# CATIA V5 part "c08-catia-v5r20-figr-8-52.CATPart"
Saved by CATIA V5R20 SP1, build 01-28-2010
Part number: Part1
Bounding box of the stored display mesh (mm): x -37.5 to 37.5, y -150 to 150, z 0 to 10
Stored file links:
  D:\v5_r20\psrt_files_downloaded\c08-catia-v5r20-prt\c08-catia-v5r20-figr-8-52.CATPart
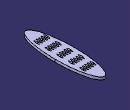
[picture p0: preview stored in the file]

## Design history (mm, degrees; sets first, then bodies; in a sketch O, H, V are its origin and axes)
Body1 (main body)
  Sketch1 on xy-plane, origin (0, 0, 0), H (1, 0, 0), V (0, 1, 0)
    circle A1 centre (0, 0) radius 75
    point P1 (0, 75)
    radius A1 = 75
    coincidence: A1 P1, P1 V
  Pad1: profile Sketch1, direction (0, 0, 1), length 10
  Sketch2 on face of Pad1, origin (0, 0, 10), H (1, 0, 0), V (0, 1, 0)
    circle A1 centre (35, -45) radius 6
    point P1 (35, -45)
    distance P1 H = 45
    distance V P1 = 35
    radius A1 = 6
  Pocket1: profile Sketch2, direction (0, 0, -1), through (limit type 3)
  RectPattern1: of Pocket1, direction 1 instances 5, spacing 19, along xy-plane reversed, direction 2 instances 5, spacing 22, along xy-plane
  Affinity1: ToTransfor RectPattern1, RatioX 0.5, RatioY 2, RatioZ 1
